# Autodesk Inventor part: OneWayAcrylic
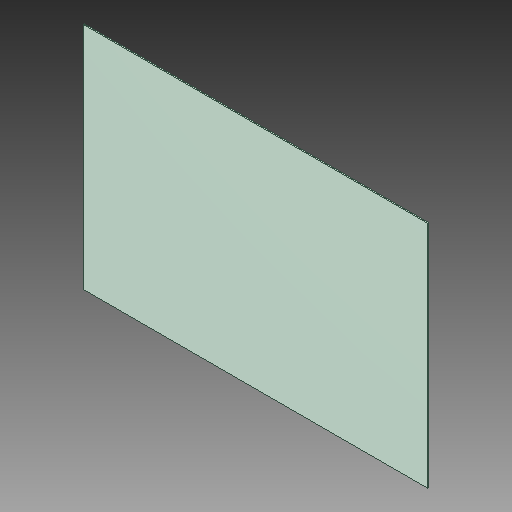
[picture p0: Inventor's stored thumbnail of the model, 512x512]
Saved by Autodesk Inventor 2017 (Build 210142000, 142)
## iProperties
Created: 2017-05
Part Number: OneWayAcrylic
Material: Generic
Document SubType Name: Modeling
Designer: Savy
Density: 1 g/cm^3
Appearance: Default
Author: Savy
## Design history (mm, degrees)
feature "SOLID1"
body "Solid1"
